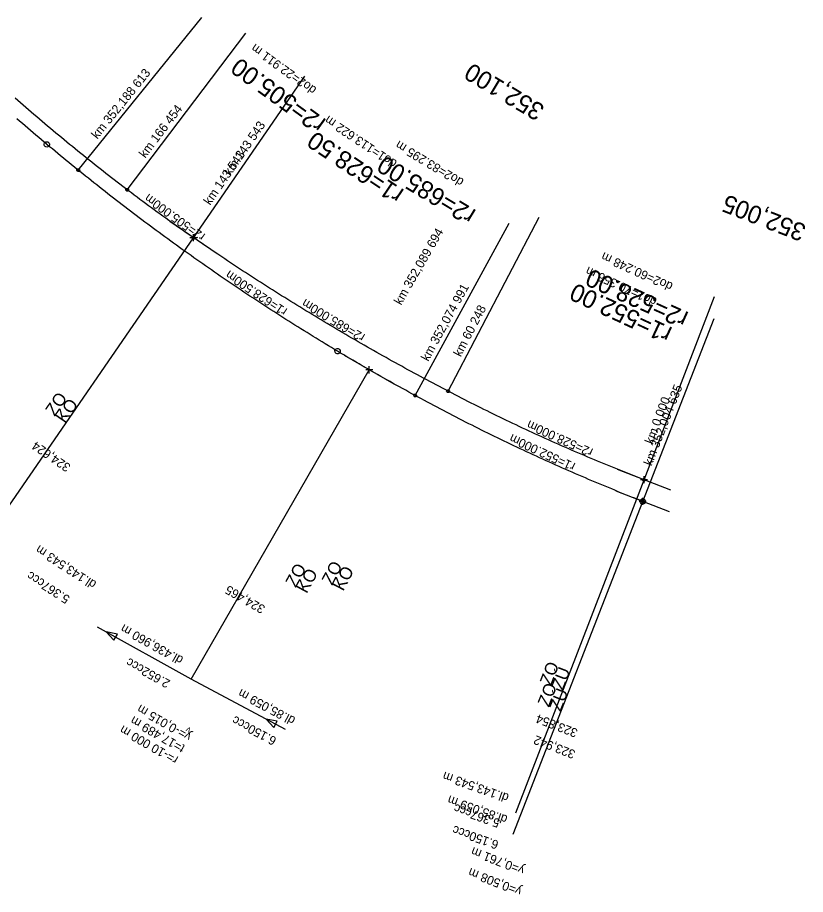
# Model space of a CAD drawing. Extents: x -825429 to 825387, y -1070027 to 1069917.
# Drawn here: x -824667.7 to -824447, y -1070026.7 to -1069781.1 of the extents above; entities that cross this region are included whole.
import ezdxf

# ---------------------------------------------------------------- set-up
doc = ezdxf.new("R2010")
doc.units = 0
doc.layers.add('NEW KOLEJE PALKOBAR', color=7, linetype='Continuous')
doc.layers.add('NEW KOLEJE VLADO PROVI', color=7, linetype='Continuous')

msp = doc.modelspace()

# ---------------------------------------------------------------- linework, layer by layer
at = {"layer": 'NEW KOLEJE PALKOBAR'}
for points in [[(-824492.23, -1069910.59), (-824493.17, -1069910.23), (-824494.1, -1069909.87), (-824495.03, -1069909.51), (-824495.96, -1069909.14), (-824496.89, -1069908.77), (-824497.82, -1069908.4), (-824498.75, -1069908.03), (-824499.68, -1069907.66), (-824500.6, -1069907.29), (-824501.53, -1069906.91), (-824502.46, -1069906.53), (-824503.38, -1069906.15), (-824504.31, -1069905.77), (-824505.23, -1069905.39), (-824506.15, -1069905), (-824507.08, -1069904.62), (-824508, -1069904.23), (-824508.92, -1069903.84), (-824509.84, -1069903.45), (-824510.76, -1069903.05), (-824511.68, -1069902.66), (-824512.59, -1069902.26), (-824513.51, -1069901.86), (-824514.43, -1069901.46), (-824515.34, -1069901.06), (-824516.26, -1069900.66), (-824517.17, -1069900.25), (-824518.08, -1069899.84), (-824519, -1069899.43), (-824519.91, -1069899.02), (-824520.82, -1069898.61), (-824521.73, -1069898.19), (-824522.64, -1069897.78), (-824523.55, -1069897.36), (-824524.45, -1069896.94), (-824525.36, -1069896.52), (-824526.27, -1069896.1), (-824527.17, -1069895.67), (-824528.08, -1069895.25), (-824528.98, -1069894.82), (-824529.88, -1069894.39), (-824530.79, -1069893.96), (-824531.69, -1069893.52), (-824532.59, -1069893.09), (-824533.49, -1069892.65), (-824534.39, -1069892.21), (-824535.28, -1069891.77), (-824536.18, -1069891.33), (-824537.08, -1069890.89), (-824537.97, -1069890.44), (-824538.87, -1069890), (-824539.76, -1069889.55), (-824540.65, -1069889.1), (-824541.55, -1069888.65), (-824542.44, -1069888.19), (-824543.33, -1069887.74), (-824544.22, -1069887.28), (-824545.11, -1069886.82), (-824545.99, -1069886.36), (-824546.88, -1069885.9), (-824547.1, -1069885.78), (-824547.77, -1069885.43), (-824548.65, -1069884.97), (-824549.54, -1069884.5), (-824550.42, -1069884.04), (-824551.3, -1069883.57), (-824552.19, -1069883.1), (-824553.07, -1069882.63), (-824553.95, -1069882.15), (-824554.83, -1069881.68), (-824555.71, -1069881.2), (-824556.59, -1069880.73), (-824557.47, -1069880.25), (-824558.35, -1069879.77), (-824559.22, -1069879.29), (-824560.1, -1069878.81), (-824560.98, -1069878.33), (-824561.85, -1069877.84), (-824562.72, -1069877.36), (-824563.6, -1069876.87), (-824564.47, -1069876.38), (-824565.34, -1069875.89), (-824566.21, -1069875.4), (-824567.08, -1069874.91), (-824567.95, -1069874.42), (-824568.82, -1069873.92), (-824569.69, -1069873.43), (-824570.56, -1069872.93), (-824571.43, -1069872.43), (-824572.29, -1069871.93), (-824573.16, -1069871.43), (-824574.02, -1069870.93), (-824574.89, -1069870.43), (-824575.75, -1069869.92), (-824576.61, -1069869.42), (-824577.48, -1069868.91), (-824578.34, -1069868.4), (-824579.2, -1069867.89), (-824580.06, -1069867.38), (-824580.92, -1069866.87), (-824581.78, -1069866.35), (-824582.63, -1069865.84), (-824583.49, -1069865.32), (-824584.35, -1069864.81), (-824585.2, -1069864.29), (-824586.05, -1069863.77), (-824586.91, -1069863.25), (-824587.76, -1069862.73), (-824588.61, -1069862.2), (-824589.46, -1069861.68), (-824590.32, -1069861.15), (-824591.17, -1069860.63), (-824592.01, -1069860.1), (-824592.86, -1069859.57), (-824593.71, -1069859.04), (-824594.56, -1069858.51), (-824595.4, -1069857.97), (-824596.25, -1069857.44), (-824597.09, -1069856.9), (-824597.94, -1069856.37), (-824598.78, -1069855.83), (-824599.62, -1069855.29), (-824600.46, -1069854.75), (-824601.3, -1069854.21), (-824602.14, -1069853.66), (-824602.98, -1069853.12), (-824603.82, -1069852.57), (-824604.66, -1069852.03), (-824605.49, -1069851.48), (-824606.33, -1069850.93), (-824607.16, -1069850.38), (-824607.17, -1069850.37), (-824608, -1069849.83), (-824608.83, -1069849.27), (-824609.66, -1069848.72), (-824610.5, -1069848.16), (-824611.33, -1069847.61), (-824612.16, -1069847.05), (-824612.99, -1069846.49), (-824613.81, -1069845.93), (-824614.64, -1069845.37), (-824615.47, -1069844.81), (-824616.29, -1069844.24), (-824617.12, -1069843.68), (-824617.94, -1069843.11), (-824618.39, -1069842.81), (-824618.77, -1069842.55), (-824619.59, -1069841.98), (-824620.41, -1069841.41), (-824621.23, -1069840.83), (-824622.05, -1069840.26), (-824622.87, -1069839.68), (-824623.69, -1069839.11), (-824624.5, -1069838.53), (-824625.32, -1069837.95), (-824626.13, -1069837.37), (-824626.94, -1069836.78), (-824627.75, -1069836.2), (-824628.56, -1069835.61), (-824629.37, -1069835.02), (-824629.43, -1069834.98), (-824630.18, -1069834.43), (-824630.98, -1069833.84), (-824631.79, -1069833.25), (-824632.59, -1069832.65), (-824633.4, -1069832.06), (-824634.2, -1069831.46), (-824635, -1069830.86), (-824635.8, -1069830.26), (-824636.59, -1069829.66), (-824636.96, -1069829.38), (-824637.39, -1069829.05), (-824638.19, -1069828.45), (-824638.98, -1069827.84), (-824639.77, -1069827.23), (-824640.57, -1069826.62), (-824641.36, -1069826.01), (-824642.15, -1069825.39), (-824642.94, -1069824.78), (-824643.72, -1069824.16), (-824644.51, -1069823.55), (-824645.3, -1069822.93), (-824646.08, -1069822.31), (-824646.86, -1069821.68), (-824647.64, -1069821.06), (-824648.42, -1069820.44), (-824649.2, -1069819.81), (-824649.98, -1069819.18), (-824650.76, -1069818.55), (-824651.54, -1069817.92), (-824652.31, -1069817.29), (-824653.09, -1069816.66), (-824653.86, -1069816.02), (-824654.63, -1069815.39), (-824655.4, -1069814.75), (-824656.17, -1069814.11), (-824656.94, -1069813.48), (-824657.71, -1069812.83), (-824658.48, -1069812.19), (-824659.24, -1069811.55), (-824660.01, -1069810.91), (-824660.77, -1069810.26), (-824661.54, -1069809.62), (-824662.3, -1069808.97), (-824663.06, -1069808.32), (-824663.82, -1069807.67), (-824664.58, -1069807.02), (-824665.34, -1069806.37), (-824666.1, -1069805.72), (-824666.85, -1069805.06), (-824667.61, -1069804.41), (-824668.36, -1069803.75)], [(-824492.6, -1069916.65), (-824492.94, -1069916.52), (-824493.87, -1069916.15), (-824494.8, -1069915.79), (-824495.73, -1069915.42), (-824496.66, -1069915.05), (-824497.59, -1069914.68), (-824498.51, -1069914.3), (-824499.44, -1069913.93), (-824500.37, -1069913.55), (-824501.29, -1069913.17), (-824502.22, -1069912.79), (-824503.14, -1069912.41), (-824504.07, -1069912.03), (-824504.99, -1069911.64), (-824505.91, -1069911.26), (-824506.83, -1069910.87), (-824507.75, -1069910.48), (-824508.67, -1069910.09), (-824509.59, -1069909.69), (-824510.51, -1069909.3), (-824511.43, -1069908.9), (-824512.35, -1069908.51), (-824513.26, -1069908.11), (-824514.18, -1069907.7), (-824515.1, -1069907.3), (-824516.01, -1069906.9), (-824516.92, -1069906.49), (-824517.84, -1069906.08), (-824518.75, -1069905.67), (-824519.66, -1069905.26), (-824520.57, -1069904.85), (-824521.48, -1069904.43), (-824522.39, -1069904.02), (-824523.3, -1069903.6), (-824524.21, -1069903.18), (-824525.11, -1069902.76), (-824526.02, -1069902.33), (-824526.92, -1069901.91), (-824527.83, -1069901.48), (-824528.73, -1069901.06), (-824529.64, -1069900.63), (-824530.54, -1069900.19), (-824531.44, -1069899.76), (-824532.34, -1069899.33), (-824533.24, -1069898.89), (-824534.14, -1069898.45), (-824535.04, -1069898.01), (-824535.94, -1069897.57), (-824536.83, -1069897.13), (-824537.73, -1069896.69), (-824538.62, -1069896.24), (-824539.52, -1069895.79), (-824540.41, -1069895.34), (-824541.3, -1069894.89), (-824542.2, -1069894.44), (-824543.09, -1069893.99), (-824543.98, -1069893.53), (-824544.87, -1069893.08), (-824545.75, -1069892.62), (-824546.64, -1069892.16), (-824547.53, -1069891.69), (-824548.42, -1069891.23), (-824549.3, -1069890.77), (-824550.18, -1069890.3), (-824551.07, -1069889.83), (-824551.95, -1069889.36), (-824552.83, -1069888.89), (-824553.71, -1069888.42), (-824553.89, -1069888.32), (-824554.59, -1069887.94), (-824555.47, -1069887.46), (-824556.34, -1069886.99), (-824556.35, -1069886.99), (-824557.23, -1069886.51), (-824558.11, -1069886.03), (-824558.98, -1069885.54), (-824559.86, -1069885.06), (-824560.73, -1069884.58), (-824561.61, -1069884.09), (-824562.48, -1069883.6), (-824563.35, -1069883.11), (-824564.22, -1069882.62), (-824565.09, -1069882.13), (-824565.96, -1069881.64), (-824566.83, -1069881.14), (-824567.7, -1069880.65), (-824568.57, -1069880.15), (-824569.17, -1069879.8), (-824569.43, -1069879.65), (-824570.3, -1069879.15), (-824571.17, -1069878.65), (-824572.03, -1069878.14), (-824572.89, -1069877.64), (-824573.76, -1069877.13), (-824574.62, -1069876.63), (-824575.48, -1069876.12), (-824576.34, -1069875.61), (-824577.2, -1069875.1), (-824578.06, -1069874.58), (-824578.91, -1069874.07), (-824579.77, -1069873.56), (-824580.63, -1069873.04), (-824581.48, -1069872.52), (-824582.34, -1069872), (-824583.19, -1069871.48), (-824584.04, -1069870.96), (-824584.2, -1069870.86), (-824584.9, -1069870.44), (-824585.75, -1069869.91), (-824586.6, -1069869.38), (-824587.45, -1069868.86), (-824588.3, -1069868.33), (-824589.14, -1069867.8), (-824589.99, -1069867.27), (-824590.84, -1069866.73), (-824591.68, -1069866.2), (-824592.53, -1069865.66), (-824593.37, -1069865.13), (-824594.21, -1069864.59), (-824595.06, -1069864.05), (-824595.9, -1069863.51), (-824596.74, -1069862.96), (-824597.58, -1069862.42), (-824598.41, -1069861.88), (-824599.25, -1069861.33), (-824600.09, -1069860.78), (-824600.92, -1069860.23), (-824601.76, -1069859.68), (-824602.59, -1069859.13), (-824603.43, -1069858.58), (-824604.26, -1069858.02), (-824605.09, -1069857.47), (-824605.92, -1069856.91), (-824606.75, -1069856.35), (-824607.58, -1069855.79), (-824608.41, -1069855.23), (-824609.23, -1069854.67), (-824610.06, -1069854.11), (-824610.89, -1069853.54), (-824611.71, -1069852.98), (-824612.53, -1069852.41), (-824613.36, -1069851.84), (-824614.18, -1069851.27), (-824615, -1069850.7), (-824615.82, -1069850.13), (-824616.64, -1069849.55), (-824617.45, -1069848.98), (-824618.27, -1069848.4), (-824619.09, -1069847.82), (-824619.9, -1069847.24), (-824620.72, -1069846.66), (-824621.53, -1069846.08), (-824622.34, -1069845.5), (-824623.15, -1069844.91), (-824623.97, -1069844.33), (-824624.77, -1069843.74), (-824625.58, -1069843.15), (-824626.39, -1069842.56), (-824627.2, -1069841.97), (-824628, -1069841.38), (-824628.81, -1069840.79), (-824629.61, -1069840.19), (-824630.42, -1069839.6), (-824631.22, -1069839), (-824632.02, -1069838.4), (-824632.82, -1069837.8), (-824633.62, -1069837.2), (-824634.42, -1069836.6), (-824635.21, -1069835.99), (-824636.01, -1069835.39), (-824636.81, -1069834.78), (-824637.6, -1069834.18), (-824638.39, -1069833.57), (-824639.19, -1069832.96), (-824639.98, -1069832.35), (-824640.77, -1069831.73), (-824641.56, -1069831.12), (-824642.35, -1069830.5), (-824643.13, -1069829.89), (-824643.92, -1069829.27), (-824644.71, -1069828.65), (-824645.49, -1069828.03), (-824646.27, -1069827.41), (-824647.06, -1069826.79), (-824647.84, -1069826.16), (-824648.62, -1069825.54), (-824649.4, -1069824.91), (-824650.18, -1069824.29), (-824650.65, -1069823.9), (-824650.96, -1069823.66), (-824651.73, -1069823.03), (-824652.51, -1069822.4), (-824653.28, -1069821.76), (-824654.06, -1069821.13), (-824654.83, -1069820.5), (-824655.6, -1069819.86), (-824656.37, -1069819.22), (-824657.14, -1069818.59), (-824657.91, -1069817.95), (-824658.68, -1069817.31), (-824659.45, -1069816.66), (-824660.21, -1069816.02), (-824660.98, -1069815.38), (-824661.74, -1069814.73), (-824662.51, -1069814.09), (-824663.27, -1069813.44), (-824664.03, -1069812.79), (-824664.79, -1069812.14), (-824665.55, -1069811.49), (-824666.31, -1069810.84), (-824667.07, -1069810.19), (-824667.82, -1069809.54)], [(-824659.93, -1069817.24), (-824660.09, -1069817.04), (-824660.18, -1069816.76), (-824660.2, -1069816.55), (-824660.12, -1069816.3), (-824659.92, -1069816.07), (-824659.72, -1069815.98), (-824659.48, -1069815.92), (-824659.19, -1069815.97), (-824658.96, -1069816.09), (-824658.8, -1069816.29), (-824658.71, -1069816.56), (-824658.69, -1069816.77), (-824658.77, -1069817.03), (-824658.97, -1069817.26), (-824659.17, -1069817.35), (-824659.42, -1069817.41), (-824659.7, -1069817.36), (-824659.93, -1069817.24)], [(-824578.44, -1069875.23), (-824578.63, -1069875.06), (-824578.77, -1069874.8), (-824578.82, -1069874.59), (-824578.78, -1069874.33), (-824578.62, -1069874.07), (-824578.44, -1069873.95), (-824578.2, -1069873.86), (-824577.91, -1069873.86), (-824577.67, -1069873.94), (-824577.48, -1069874.11), (-824577.35, -1069874.37), (-824577.29, -1069874.58), (-824577.34, -1069874.84), (-824577.49, -1069875.1), (-824577.68, -1069875.22), (-824577.91, -1069875.31), (-824578.2, -1069875.31), (-824578.44, -1069875.23)], [(-824492.87, -1069917.35), (-824493.08, -1069917.21), (-824493.26, -1069916.98), (-824493.35, -1069916.79), (-824493.35, -1069916.52), (-824493.24, -1069916.24), (-824493.08, -1069916.09), (-824492.86, -1069915.96), (-824492.58, -1069915.91), (-824492.32, -1069915.95), (-824492.11, -1069916.09), (-824491.93, -1069916.32), (-824491.85, -1069916.51), (-824491.84, -1069916.78), (-824491.95, -1069917.06), (-824492.12, -1069917.21), (-824492.33, -1069917.34), (-824492.62, -1069917.39), (-824492.87, -1069917.35)]]:
    msp.add_lwpolyline(points, dxfattribs=at)
at = {"layer": 'NEW KOLEJE VLADO PROVI'}
for p, q in [((-824617.39, -1069842.81), (-824619.39, -1069842.81)), ((-824618.39, -1069843.81), (-824618.39, -1069841.81)), ((-824568.17, -1069879.8), (-824570.17, -1069879.8)), ((-824569.17, -1069880.8), (-824569.17, -1069878.8)), ((-824491.23, -1069910.59), (-824493.23, -1069910.59)), ((-824492.23, -1069911.59), (-824492.23, -1069909.59)), ((-824491.6, -1069916.65), (-824493.6, -1069916.65)), ((-824492.6, -1069917.65), (-824492.6, -1069915.65)), ((-824639.71, -1069953.8), (-824642.82, -1069953.22)), ((-824642.82, -1069953.22), (-824640.69, -1069955.55)), ((-824640.69, -1069955.55), (-824639.71, -1069953.8)), ((-824594.95, -1069978.2), (-824598.07, -1069977.67)), ((-824598.07, -1069977.67), (-824595.89, -1069979.97)), ((-824595.89, -1069979.97), (-824594.95, -1069978.2))]:
    msp.add_line(p, q, dxfattribs=at)
for points in [[(-824650.65, -1069823.9), (-824616.07, -1069781.13)], [(-824636.96, -1069829.38), (-824603.73, -1069785.55)], [(-824618.39, -1069842.81), (-824587.19, -1069797.51)], [(-824650.91, -1069824.21), (-824650.99, -1069824.11), (-824651.05, -1069823.96), (-824651.06, -1069823.85), (-824651.02, -1069823.71), (-824650.92, -1069823.59), (-824650.81, -1069823.54), (-824650.68, -1069823.51), (-824650.52, -1069823.53), (-824650.4, -1069823.59), (-824650.32, -1069823.69), (-824650.26, -1069823.84), (-824650.25, -1069823.95), (-824650.29, -1069824.09), (-824650.39, -1069824.22), (-824650.5, -1069824.26), (-824650.63, -1069824.3), (-824650.79, -1069824.28), (-824650.91, -1069824.21)], [(-824637.2, -1069829.7), (-824637.29, -1069829.6), (-824637.35, -1069829.45), (-824637.36, -1069829.34), (-824637.32, -1069829.2), (-824637.23, -1069829.08), (-824637.12, -1069829.02), (-824636.99, -1069828.99), (-824636.84, -1069829), (-824636.72, -1069829.06), (-824636.63, -1069829.17), (-824636.57, -1069829.31), (-824636.55, -1069829.42), (-824636.59, -1069829.56), (-824636.69, -1069829.69), (-824636.79, -1069829.74), (-824636.92, -1069829.78), (-824637.08, -1069829.76), (-824637.2, -1069829.7)], [(-824547.1, -1069885.78), (-824521.62, -1069837.04)], [(-824611.8, -1069847.34), (-824624.98, -1069838.27)], [(-824556.34, -1069886.99), (-824530.02, -1069838.7)], [(-824675.13, -1069925.15), (-824618.39, -1069842.81)], [(-824618.62, -1069843.13), (-824618.71, -1069843.04), (-824618.78, -1069842.9), (-824618.8, -1069842.78), (-824618.77, -1069842.64), (-824618.68, -1069842.51), (-824618.57, -1069842.45), (-824618.44, -1069842.41), (-824618.29, -1069842.42), (-824618.16, -1069842.48), (-824618.07, -1069842.57), (-824618.01, -1069842.71), (-824617.99, -1069842.83), (-824618.02, -1069842.97), (-824618.11, -1069843.1), (-824618.21, -1069843.16), (-824618.34, -1069843.2), (-824618.49, -1069843.19), (-824618.62, -1069843.13)], [(-824492.23, -1069910.59), (-824472.47, -1069859.27)], [(-824492.6, -1069916.65), (-824472.62, -1069865.41)], [(-824562.24, -1069883.79), (-824576.1, -1069875.81)], [(-824619.08, -1069966.45), (-824569.17, -1069879.8)], [(-824556.54, -1069887.34), (-824556.64, -1069887.25), (-824556.72, -1069887.12), (-824556.75, -1069887.01), (-824556.73, -1069886.87), (-824556.66, -1069886.73), (-824556.56, -1069886.66), (-824556.44, -1069886.61), (-824556.28, -1069886.6), (-824556.15, -1069886.64), (-824556.05, -1069886.73), (-824555.97, -1069886.86), (-824555.94, -1069886.97), (-824555.95, -1069887.11), (-824556.03, -1069887.25), (-824556.13, -1069887.32), (-824556.25, -1069887.38), (-824556.41, -1069887.38), (-824556.54, -1069887.34)], [(-824547.29, -1069886.14), (-824547.39, -1069886.05), (-824547.47, -1069885.92), (-824547.51, -1069885.81), (-824547.49, -1069885.67), (-824547.42, -1069885.53), (-824547.32, -1069885.46), (-824547.2, -1069885.4), (-824547.05, -1069885.39), (-824546.92, -1069885.43), (-824546.81, -1069885.51), (-824546.73, -1069885.65), (-824546.7, -1069885.75), (-824546.71, -1069885.9), (-824546.78, -1069886.04), (-824546.88, -1069886.11), (-824547, -1069886.17), (-824547.16, -1069886.18), (-824547.29, -1069886.14)], [(-824484.77, -1069913.47), (-824499.7, -1069907.72)], [(-824528.17, -1070003.91), (-824492.23, -1069910.59)], [(-824492.38, -1069910.97), (-824492.49, -1069910.89), (-824492.59, -1069910.77), (-824492.63, -1069910.67), (-824492.64, -1069910.52), (-824492.58, -1069910.37), (-824492.49, -1069910.29), (-824492.38, -1069910.22), (-824492.22, -1069910.2), (-824492.09, -1069910.22), (-824491.98, -1069910.29), (-824491.88, -1069910.42), (-824491.83, -1069910.52), (-824491.83, -1069910.66), (-824491.89, -1069910.81), (-824491.98, -1069910.89), (-824492.09, -1069910.96), (-824492.24, -1069910.99), (-824492.38, -1069910.97)], [(-824485.14, -1069919.55), (-824500.05, -1069913.74)], [(-824528.92, -1070009.82), (-824492.6, -1069916.65)], [(-824492.74, -1069917.02), (-824492.86, -1069916.95), (-824492.95, -1069916.83), (-824493, -1069916.72), (-824493, -1069916.58), (-824492.94, -1069916.43), (-824492.85, -1069916.35), (-824492.74, -1069916.28), (-824492.59, -1069916.25), (-824492.45, -1069916.28), (-824492.34, -1069916.35), (-824492.24, -1069916.47), (-824492.2, -1069916.58), (-824492.2, -1069916.72), (-824492.25, -1069916.87), (-824492.34, -1069916.95), (-824492.46, -1069917.02), (-824492.61, -1069917.05), (-824492.74, -1069917.02)], [(-824619.08, -1069966.45), (-824645.28, -1069951.84)], [(-824592.62, -1069980.58), (-824619.08, -1069966.45)]]:
    msp.add_lwpolyline(points, dxfattribs=at)

# ---------------------------------------------------------------- texts
at = {"layer": 'NEW KOLEJE PALKOBAR'}
for s, rotation, p in [('352,100', 149.2085, (-824519.74, -1069806.02)), ('352,005', 158.7911, (-824446.51, -1069839.34))]:
    msp.add_text(s, height=5, rotation=rotation, dxfattribs=at).set_placement(p)
at = {"layer": 'NEW KOLEJE VLADO PROVI'}
for s, height, rotation, p in [('do2=22.911 m', 2.5, 144.1328, (-824583.74, -1069800.92)), ('r2=505.00', 5, 144.1328, (-824580.95, -1069809.88)), ('km 352,188 613', 2.5, 51.0403, (-824645.34, -1069815.34)), ('km 166 454', 2.5, 52.8331, (-824631.91, -1069820.66)), ('do1=113.622 m', 2.5, 146.2193, (-824561.19, -1069821.42)), ('km 143 543', 2.5, 55.4325, (-824608.07, -1069825.63)), ('r1=628.50', 5, 146.2193, (-824559.12, -1069829.57)), ('do2=83.295 m', 2.5, 148.916, (-824542.48, -1069826.56)), ('km 143 543', 2.5, 55.4325, (-824613.75, -1069833.86)), ('r2=685.00', 5, 148.916, (-824538.96, -1069835.24)), ('r2=505.000m', 2.5, 144.1328, (-824614.92, -1069841.93)), ('km 352,089 694', 2.5, 60.058, (-824560.27, -1069861.85)), ('do2=60.248 m', 2.5, 155.6685, (-824483.95, -1069855.61)), ('r1=628.500m', 2.5, 146.2193, (-824591.9, -1069862.83)), ('do1=70.356 m', 2.5, 155.0497, (-824488.41, -1069859.86)), ('r2=528.00', 5, 155.6685, (-824479.43, -1069863.82)), ('km 352,074 991', 2.5, 61.3984, (-824552.65, -1069877.61)), ('r1=552.00', 5, 155.0497, (-824483.98, -1069868.13)), ('r2=685.000m', 2.5, 148.916, (-824570.14, -1069870.01)), ('km 60 248', 2.5, 62.3996, (-824543.58, -1069876.34)), ('km 352,004 635', 2.5, 68.7011, (-824490.13, -1069906.88)), ('ZO', 3.5, 55.4325, (-824657.25, -1069893.02)), ('KO', 3.5, 55.4325, (-824654.36, -1069895.01)), ('km 0 000', 2.5, 68.9374, (-824489.81, -1069900.81)), ('r2=528.000m', 2.5, 155.6685, (-824506.31, -1069902.02)), ('r1=552.000m', 2.5, 155.0497, (-824511.26, -1069906.03)), ('324,624', 2.5, 145.4334, (-824652.58, -1069906.53)), ('dl.143,543 m', 2.5, 147.0427, (-824645.36, -1069939.28)), ('ZO', 3.5, 62.3996, (-824579.58, -1069940.34)), ('ZO', 3.5, 61.3984, (-824589.77, -1069940.98)), ('KO', 3.5, 61.3984, (-824586.7, -1069942.65)), ('KO', 3.5, 62.3996, (-824576.48, -1069941.97)), ('5.367ccc', 2.5, 147.0427, (-824652.79, -1069943.4)), ('324,465', 2.5, 150.0589, (-824598.11, -1069946.08)), ('dl.436,960 m', 2.5, 150.8536, (-824621.04, -1069960.36)), ('2.652ccc', 2.5, 150.8536, (-824624.7, -1069966.91)), ('ZO', 3.5, 68.9374, (-824518.29, -1069968.5)), ('ZÚ', 3.5, 68.9374, (-824515.02, -1069969.76)), ('ZO', 3.5, 68.7011, (-824518.89, -1069974.45)), ('dl.85,059 m', 2.5, 151.903, (-824589.65, -1069977.27)), ('ZÚ', 3.5, 68.7011, (-824515.63, -1069975.72)), ('y=-0,015 m', 2.5, 150.0589, (-824618.7, -1069981.82)), ('t=17,489 m', 2.5, 150.0589, (-824620.57, -1069985.07)), ('6.150ccc', 2.5, 151.903, (-824594.94, -1069982.94)), ('323,854', 2.5, 158.9383, (-824510.6, -1069980.54)), ('r=-10 000 m', 2.5, 150.0589, (-824622.44, -1069988.32)), ('v', 1.8, 150.0589, (-824618.96, -1069980.27)), ('323,942', 2.5, 158.702, (-824511.25, -1069986.52)), ('dl.143,543 m', 2.5, 160.5476, (-824529.87, -1069998.71)), ('dl.85,059 m', 2.5, 160.5461, (-824530.25, -1070004.76)), ('5.367ccc', 2.5, 160.5476, (-824532.37, -1070005.78)), ('6.150ccc', 2.5, 160.5461, (-824532.75, -1070011.83)), ('y=0,761 m', 2.5, 158.9383, (-824525.42, -1070019.04)), ('y=0,508 m', 2.5, 158.702, (-824526.23, -1070024.95))]:
    msp.add_text(s, height=height, rotation=rotation, dxfattribs=at).set_placement(p)

doc.saveas('drawing.dxf')
